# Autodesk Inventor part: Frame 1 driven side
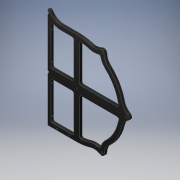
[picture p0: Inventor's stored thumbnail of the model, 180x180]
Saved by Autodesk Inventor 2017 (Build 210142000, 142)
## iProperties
Created: 2016-06
Part Number: Frame 1 driven side
Material: Generic
Document SubType Name: Modeling
Designer: Stan
Density: 1 g/cm^3
Appearance: Glossy - Black
Author: Stan
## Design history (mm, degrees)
sketch "Sketch1"
  geometry: L1 (-33.07, 98.425)-(0, 98.425); L2 (-33.07, 88.9)-(-9.525, 88.9); L3 (-60.566, -98.425)-(0, -98.425); L4 (-51.041, -9.525)-(-9.525, -9.525); L5 (9.525, -9.525)-(85.613, -9.525); L6 (-51.041, 9.525)-(-9.525, 9.525); L7 (9.525, 9.525)-(85.613, 9.525); L8 (-51.041, -88.9)-(-9.525, -88.9); L9 (-6.35, -12.7)-(-6.35, -85.725); L10 (6.35, -12.7)-(6.35, -85.194); L11 (-6.35, 12.7)-(-6.35, 85.725); L12 (6.35, 12.7)-(6.35, 85.194); L13 (-60.566, 114.3)-(-60.566, 110.49); L14 (-60.566, 105.41)-(-60.566, -98.425); L15 (-54.216, 90.23)-(-54.216, 12.7); L16 (-54.216, -12.7)-(-54.216, -85.725); C1 r 2.54 at (104.775, 0); C2 r 2.54 at (52.387, -90.738); C3 r 2.54 at (52.388, 90.738); A1 r 3.175 centre (-9.525, 85.725) between (-6.35, 85.725) and (-9.525, 88.9); A2 r 3.175 centre (-51.041, -12.7) between (-51.041, -9.525) and (-54.216, -12.7); A3 r 3.175 centre (-9.525, -12.7) between (-6.35, -12.7) and (-9.525, -9.525); A4 r 3.175 centre (-9.525, 12.7) between (-9.525, 9.525) and (-6.35, 12.7); A5 r 3.175 centre (9.525, 12.7) between (6.35, 12.7) and (9.525, 9.525); A6 r 98.425 centre (0, 0) between (0, -98.425) and (29.099, -94.025); A7 r 98.425 centre (0, 0) between (66.878, -72.213) and (95.978, -21.812); A8 r 98.425 centre (0, 0) between (95.978, 21.812) and (66.878, 72.213); A9 r 98.425 centre (0, 0) between (29.099, 94.025) and (0, 98.425); A10 r 88.9 centre (0, 0) between (9.878, -88.35) and (26.283, -84.926); A11 r 88.9 centre (0, 0) between (60.406, -65.225) and (86.69, -19.701); A12 r 3.175 centre (9.525, -85.194) between (6.35, -85.194) and (9.878, -88.35); A13 r 88.9 centre (0, 0) between (86.69, 19.701) and (60.406, 65.225); A14 r 88.9 centre (0, 0) between (26.283, 84.926) and (9.878, 88.35); A15 r 3.175 centre (9.525, 85.194) between (9.878, 88.35) and (6.35, 85.194); A16 r 6.35 centre (104.775, 0) between (107.969, -5.488) and (107.969, 5.488); A17 r 25.4 centre (120.746, 27.441) between (95.978, 21.812) and (107.969, 5.488); A18 r 34.925 centre (120.746, 27.441) between (86.69, 19.701) and (88.541, 13.928); A19 r 3.175 centre (85.613, 12.7) between (85.613, 9.525) and (88.541, 13.928); A20 r 25.4 centre (120.746, -27.441) between (107.969, -5.488) and (95.978, -21.812); A21 r 34.925 centre (120.746, -27.441) between (88.541, -13.928) and (86.69, -19.701); A22 r 3.175 centre (85.613, -12.7) between (88.541, -13.928) and (85.613, -9.525); A23 r 6.35 centre (52.387, -90.738) between (49.232, -96.248) and (58.737, -90.76); A24 r 25.4 centre (84.137, -90.849) between (66.878, -72.213) and (58.737, -90.76); A25 r 34.925 centre (84.137, -90.849) between (60.406, -65.225) and (50.239, -82.443); A26 r 25.4 centre (36.609, -118.29) between (49.232, -96.248) and (29.099, -94.025); A27 r 34.925 centre (36.609, -118.29) between (46.278, -84.73) and (26.283, -84.926); A28 r 3.175 centre (47.157, -81.679) between (46.278, -84.73) and (50.239, -82.443); A29 r 6.35 centre (52.388, 90.738) between (58.737, 90.76) and (49.232, 96.248); A30 r 25.4 centre (36.609, 118.29) between (29.099, 94.025) and (49.232, 96.248); A31 r 34.925 centre (36.609, 118.29) between (26.283, 84.926) and (46.278, 84.73); A32 r 25.4 centre (84.137, 90.849) between (58.737, 90.76) and (66.878, 72.213); A33 r 34.925 centre (84.137, 90.849) between (50.239, 82.443) and (60.406, 65.225); A34 r 3.175 centre (47.157, 81.679) between (50.239, 82.443) and (46.278, 84.73); A35 r 6.35 centre (-60.566, 107.95) between (-55.067, 111.125) and (-60.566, 114.3); A36 r 25.4 centre (-33.07, 123.825) between (-55.067, 111.125) and (-33.07, 98.425); A37 r 34.925 centre (-33.07, 123.825) between (-49.544, 93.029) and (-33.07, 88.9); A38 r 3.175 centre (-51.041, 90.23) between (-49.544, 93.029) and (-54.216, 90.23); A39 r 2.54 centre (-60.566, 107.95) between (-60.566, 105.41) and (-60.566, 110.49); A40 r 3.175 centre (-9.525, -85.725) between (-9.525, -88.9) and (-6.35, -85.725); A41 r 3.175 centre (9.525, -12.7) between (9.525, -9.525) and (6.35, -12.7); A42 r 3.175 centre (-51.041, 12.7) between (-54.216, 12.7) and (-51.041, 9.525); A43 r 3.175 centre (-51.041, -85.725) between (-54.216, -85.725) and (-51.041, -88.9); 1 further point
  constraints: 86 point on circle, 46 centre point, 32 end point
workplane "Work Plane2"
sketch "Sketch2"
  geometry: L1 (0, 0)-(0, 203.835) reference; C1 r 1.587 at (3.175, 177.8); C2 r 1.587 at (3.175, 117.475); C3 r 1.587 at (3.175, 79.375); C4 r 1.587 at (3.175, 19.05); 3 further points
  constraints: 4 centre point
  dimensions: "d3" = 3.175 diameter of C1; "d4" = 3.175 diameter of C2; "d5" = 3.175 diameter of C3; "d6" = 3.175 diameter of C4; "d7" = 3.175 distance from line of L1 C1.centre; "d8" = 3.175 distance from line of L1 C2.centre; "d9" = 3.175 distance from line of L1 C3.centre; "d10" = 3.175 distance from line of L1 C4.centre; "d11" = 60.325 distance of C3.centre C4.centre; "d12" = 9.525 vertical distance of C3.centre point (4.763, 88.9); "d13" = 9.525 vertical distance of C2.centre point (4.763, 107.95); "d14" = 60.325 distance of C2.centre C1.centre
extrude "Extrusion4" new body sketch "Sketch1" distance "d24" = 6.35; taper "d25" = 0 deg
extrude "Extrusion5" cut sketch "Sketch2" distance "d26" = 6.35; taper "d27" = 0 deg
fillet "Fillet2" dims "d28" = 0.79375
sketch "Sketch4"
  geometry: C1 r 1.587 at (0, 0); 1 further point
  constraints: 1 centre point, 1 coincident
  dimensions: "d29" = 3.175 diameter of C1
extrude "Extrusion6" cut sketch "Sketch4" distance "d30" = 6.35; taper "d31" = 0 deg
sketch "Sketch5"
  geometry: L1 (-60.566, 105.41)-(-60.566, -97.631) reference; L2 (-60.566, 2.54)-(-60.566, -2.54); A1 r 2.54 centre (-60.566, 0) between (-60.566, -2.54) and (-60.566, 2.54); 1 further point
  constraints: 3 point on line, 2 end point, 2 point on circle, 1 centre point
  dimensions: "d32" = 5.08 diameter of A1
extrude "Extrusion7" cut sketch "Sketch5" distance "d33" = 6.35; taper "d34" = 0 deg
fillet "Fillet3" dims "d35" = 0.79375
sketch "Sketch6"
  geometry: L1 (-60.566, -2.54)-(-60.566, -97.631) reference; L2 (-60.566, -98.425)-(0, -98.425) reference; C1 r 2.54 at (-41.516, -93.663); C2 r 2.54 at (-16.116, -93.663); 1 further point
  constraints: 2 centre point
  dimensions: "d36" = 5.08 diameter of C1; "d37" = 19.05 distance from line of C1.centre L1; "d38" = 5.08 diameter of C2; "d39" = 25.4 distance of C2.centre C1.centre; "d40" = 4.7625 distance from line of L2 C1.centre; "d41" = 4.7625 distance from line of L2 C2.centre
extrude "Extrusion8" cut sketch "Sketch6" distance "d42" = 6.35; taper "d43" = 0 deg
body "Solid2"
